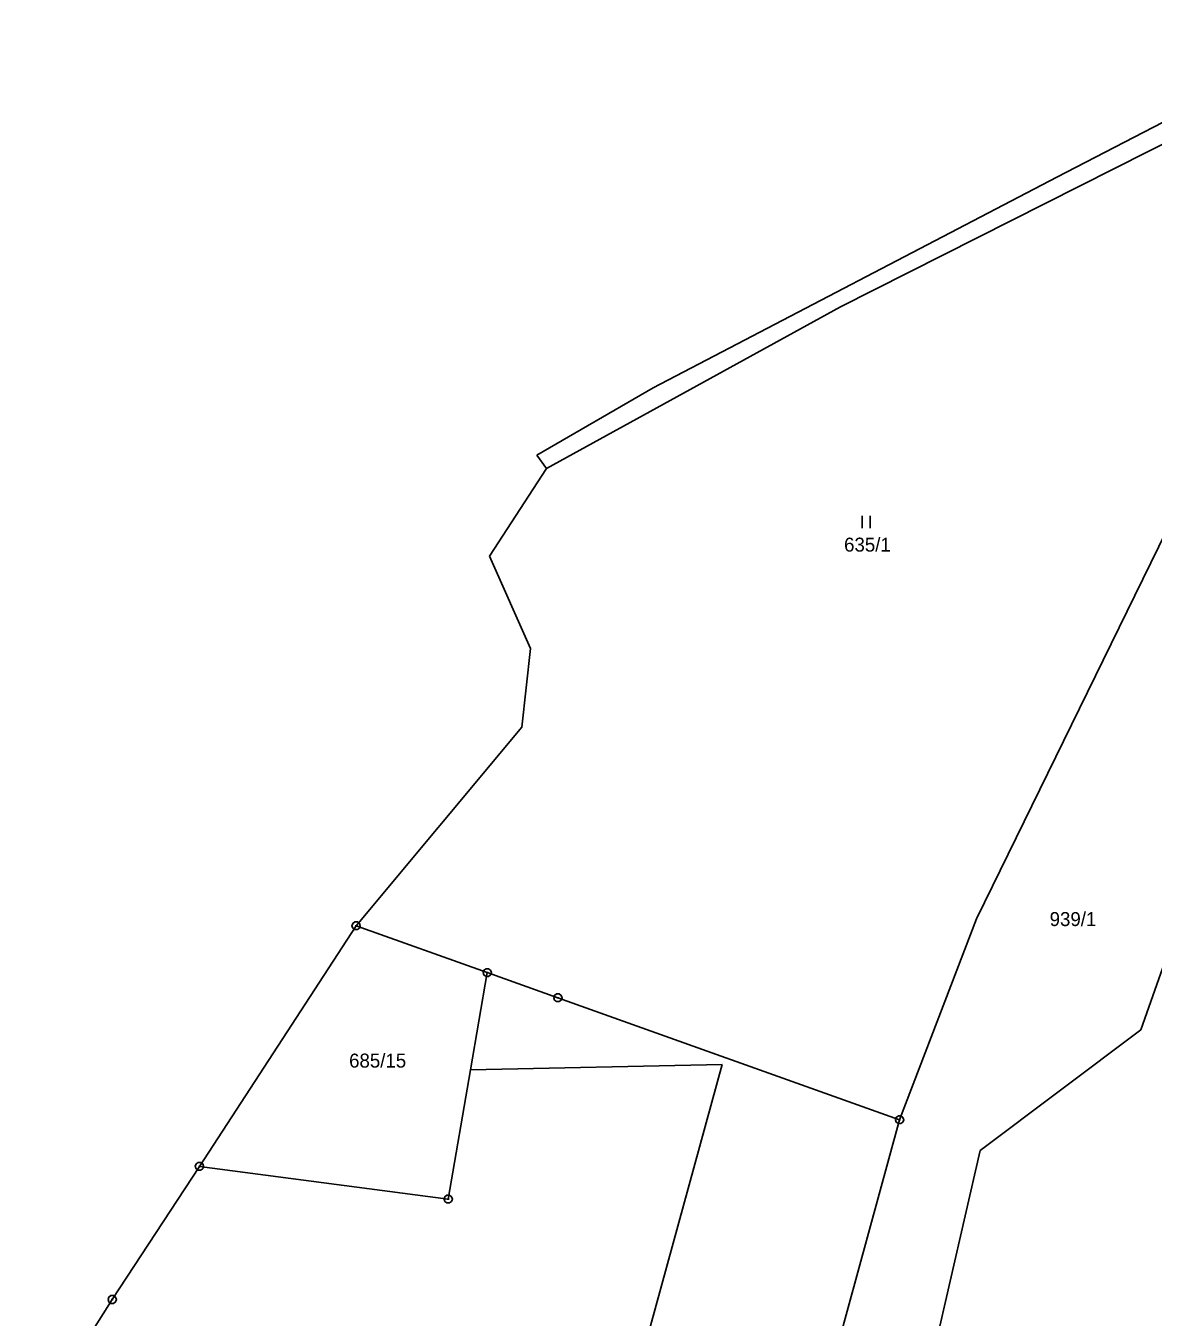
# Model space of a CAD drawing. Extents: x -580551 to -575069, y -1073031 to -1067931.
# Drawn here: x -578482.3 to -578344.9, y -1070721.5 to -1070564.2 of the extents above; entities that cross this region are included whole.
import ezdxf

# ---------------------------------------------------------------- set-up
doc = ezdxf.new("R2010")
doc.units = 0
for name, color, linetype in [('Druh pozemku', 7, 'Continuous'), ('Geodetické body', 7, 'Continuous'), ('Katastrální hranice', 7, 'Continuous'), ('Parcela', 7, 'Continuous'), ('Parcelní číslo', 7, 'Continuous')]:
    doc.layers.add(name, color=color, linetype=linetype)

msp = doc.modelspace()

# ---------------------------------------------------------------- linework, layer by layer
at = {"layer": 'Druh pozemku'}
for p, q in [((-578380.4, -1070623.91), (-578380.4, -1070625.41)), ((-578379.4, -1070625.41), (-578379.4, -1070623.91))]:
    msp.add_line(p, q, dxfattribs=at)
at = {"layer": 'Geodetické body'}
for p, q in [((-578442.15, -1070673.81), (-578441.91, -1070673.81)), ((-578426.17, -1070679.51), (-578425.93, -1070679.51)), ((-578417.57, -1070682.58), (-578417.33, -1070682.58)), ((-578375.94, -1070697.43), (-578375.7, -1070697.43)), ((-578461.24, -1070703.1), (-578461, -1070703.1)), ((-578430.93, -1070707.09), (-578430.69, -1070707.09)), ((-578471.86, -1070719.32), (-578471.62, -1070719.32))]:
    msp.add_line(p, q, dxfattribs=at)
for points in [[(-578441.88, -1070673.33), (-578441.63, -1070673.51), (-578441.53, -1070673.8), (-578441.63, -1070674.09), (-578441.88, -1070674.27), (-578442.19, -1070674.27), (-578442.44, -1070674.09), (-578442.54, -1070673.8), (-578442.44, -1070673.51), (-578442.19, -1070673.33)], [(-578425.9, -1070679.03), (-578425.65, -1070679.21), (-578425.55, -1070679.5), (-578425.65, -1070679.79), (-578425.9, -1070679.97), (-578426.21, -1070679.97), (-578426.46, -1070679.79), (-578426.56, -1070679.5), (-578426.46, -1070679.21), (-578426.21, -1070679.03)], [(-578417.3, -1070682.1), (-578417.05, -1070682.28), (-578416.95, -1070682.57), (-578417.05, -1070682.86), (-578417.3, -1070683.04), (-578417.61, -1070683.04), (-578417.86, -1070682.86), (-578417.96, -1070682.57), (-578417.86, -1070682.28), (-578417.61, -1070682.1)], [(-578375.67, -1070696.95), (-578375.42, -1070697.13), (-578375.32, -1070697.42), (-578375.42, -1070697.71), (-578375.67, -1070697.89), (-578375.98, -1070697.89), (-578376.23, -1070697.71), (-578376.33, -1070697.42), (-578376.23, -1070697.13), (-578375.98, -1070696.95)], [(-578460.97, -1070702.62), (-578460.72, -1070702.8), (-578460.62, -1070703.09), (-578460.72, -1070703.38), (-578460.97, -1070703.56), (-578461.28, -1070703.56), (-578461.53, -1070703.38), (-578461.63, -1070703.09), (-578461.53, -1070702.8), (-578461.28, -1070702.62)], [(-578430.66, -1070706.61), (-578430.41, -1070706.79), (-578430.31, -1070707.08), (-578430.41, -1070707.37), (-578430.66, -1070707.55), (-578430.97, -1070707.55), (-578431.22, -1070707.37), (-578431.32, -1070707.08), (-578431.22, -1070706.79), (-578430.97, -1070706.61)], [(-578471.59, -1070718.84), (-578471.34, -1070719.02), (-578471.24, -1070719.31), (-578471.34, -1070719.6), (-578471.59, -1070719.78), (-578471.9, -1070719.78), (-578472.15, -1070719.6), (-578472.25, -1070719.31), (-578472.15, -1070719.02), (-578471.9, -1070718.84)]]:
    msp.add_lwpolyline(points, close=True, dxfattribs=at)
at = {"layer": 'Katastrální hranice'}
for p, q in [((-578356.67, -1070582.67), (-578321.11, -1070564.23)), ((-578405.85, -1070608.31), (-578356.67, -1070582.67)), ((-578420, -1070616.49), (-578405.85, -1070608.31)), ((-578418.84, -1070618.14), (-578420, -1070616.49)), ((-578425.77, -1070628.8), (-578418.84, -1070618.14)), ((-578420.78, -1070640.05), (-578425.77, -1070628.8)), ((-578421.85, -1070649.62), (-578420.78, -1070640.05)), ((-578442.03, -1070673.81), (-578421.85, -1070649.62)), ((-578461.12, -1070703.1), (-578442.03, -1070673.81)), ((-578471.74, -1070719.32), (-578461.12, -1070703.1)), ((-578472.83, -1070721.04), (-578471.74, -1070719.32)), ((-578482.27, -1070735.9), (-578472.83, -1070721.04))]:
    msp.add_line(p, q, dxfattribs=at)
at = {"layer": 'Parcela'}
for p, q in [((-578325.66, -1070569.48), (-578383.01, -1070598.43)), ((-578383.01, -1070598.43), (-578418.84, -1070618.14)), ((-578338.75, -1070616.37), (-578366.44, -1070672.97)), ((-578346.44, -1070686.49), (-578334.57, -1070652.72)), ((-578366.44, -1070672.97), (-578375.82, -1070697.43)), ((-578442.03, -1070673.81), (-578426.05, -1070679.51)), ((-578426.05, -1070679.51), (-578428.09, -1070691.34)), ((-578426.05, -1070679.51), (-578417.45, -1070682.58)), ((-578417.45, -1070682.58), (-578375.82, -1070697.43)), ((-578366.02, -1070701.17), (-578346.44, -1070686.49)), ((-578397.46, -1070690.68), (-578429.77, -1070808.85)), ((-578428.09, -1070691.34), (-578397.46, -1070690.68)), ((-578428.09, -1070691.34), (-578430.81, -1070707.09)), ((-578375.82, -1070697.43), (-578386.72, -1070737.22)), ((-578376.34, -1070746.25), (-578366.02, -1070701.17)), ((-578430.81, -1070707.09), (-578461.12, -1070703.1))]:
    msp.add_line(p, q, dxfattribs=at)

# ---------------------------------------------------------------- texts
at = {"layer": 'Parcelní číslo'}
for s, p in [('635/1', (-578382.59, -1070628.25)), ('939/1', (-578357.549, -1070673.84)), ('685/15', (-578442.887, -1070691.07))]:
    msp.add_text(s, height=1.7, dxfattribs=at).set_placement(p)

doc.saveas('drawing.dxf')
